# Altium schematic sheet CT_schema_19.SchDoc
size 634 x 434 mm
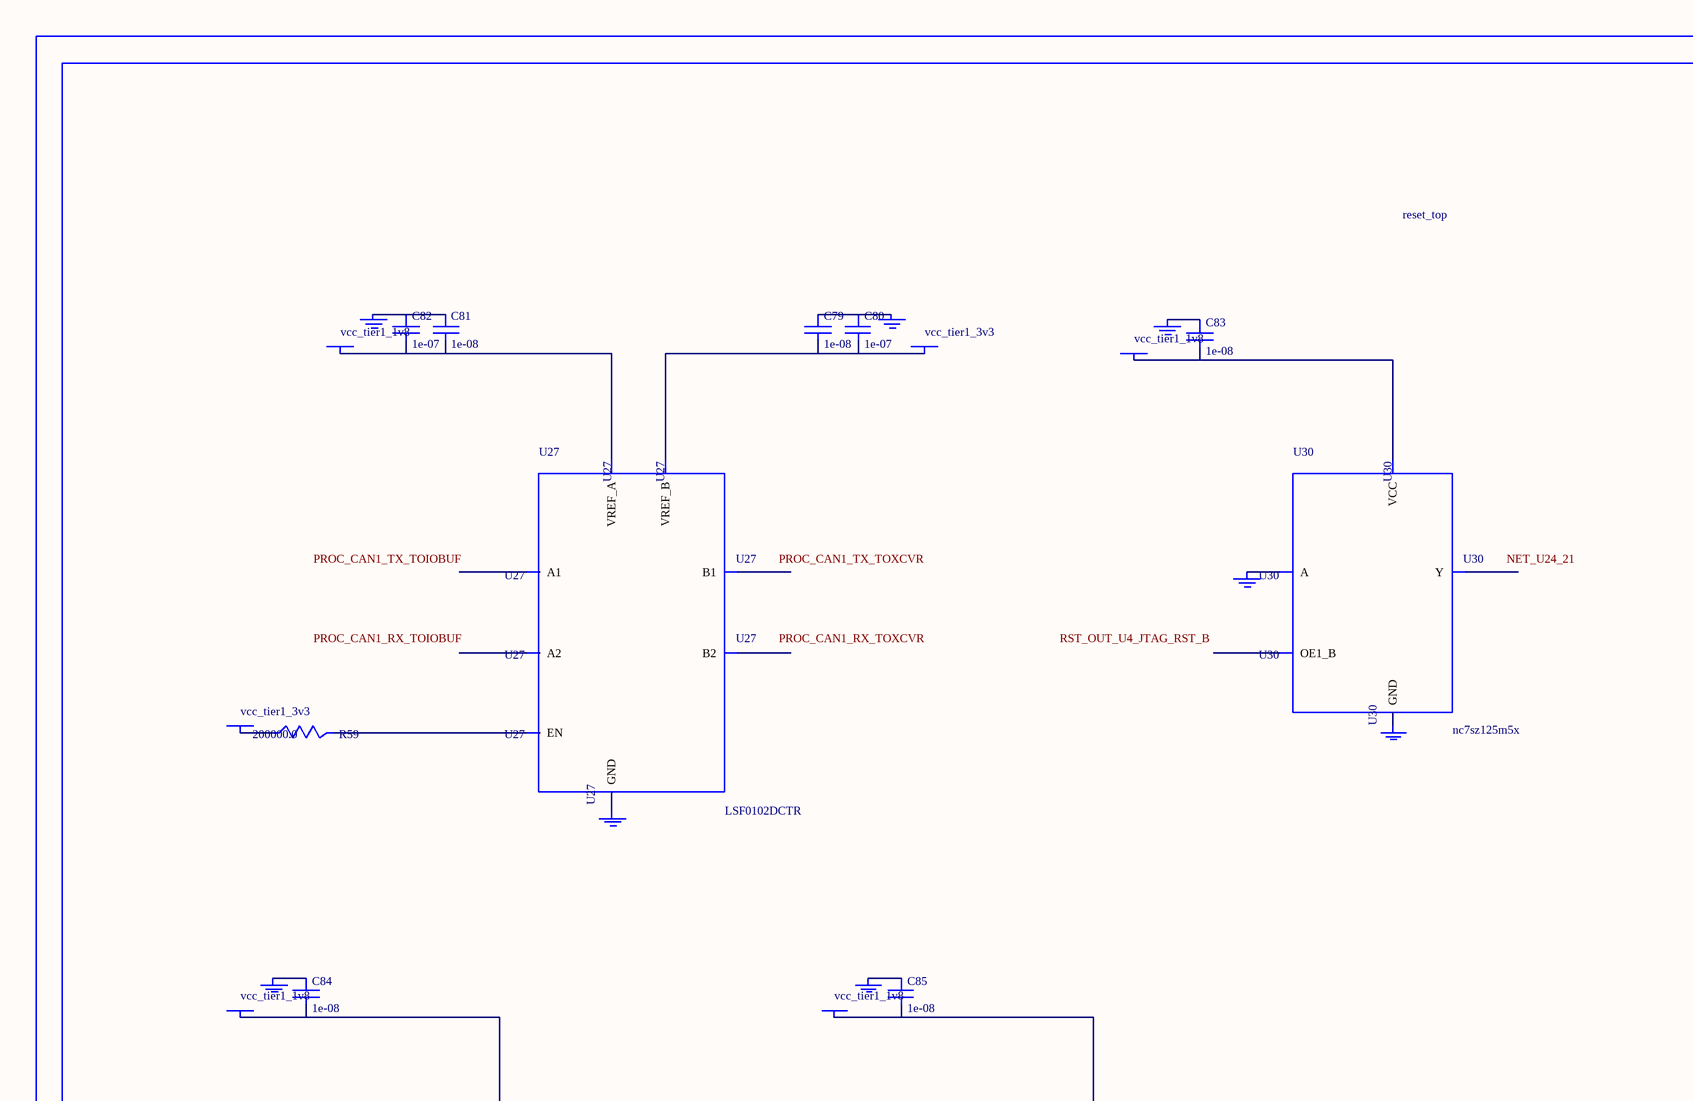
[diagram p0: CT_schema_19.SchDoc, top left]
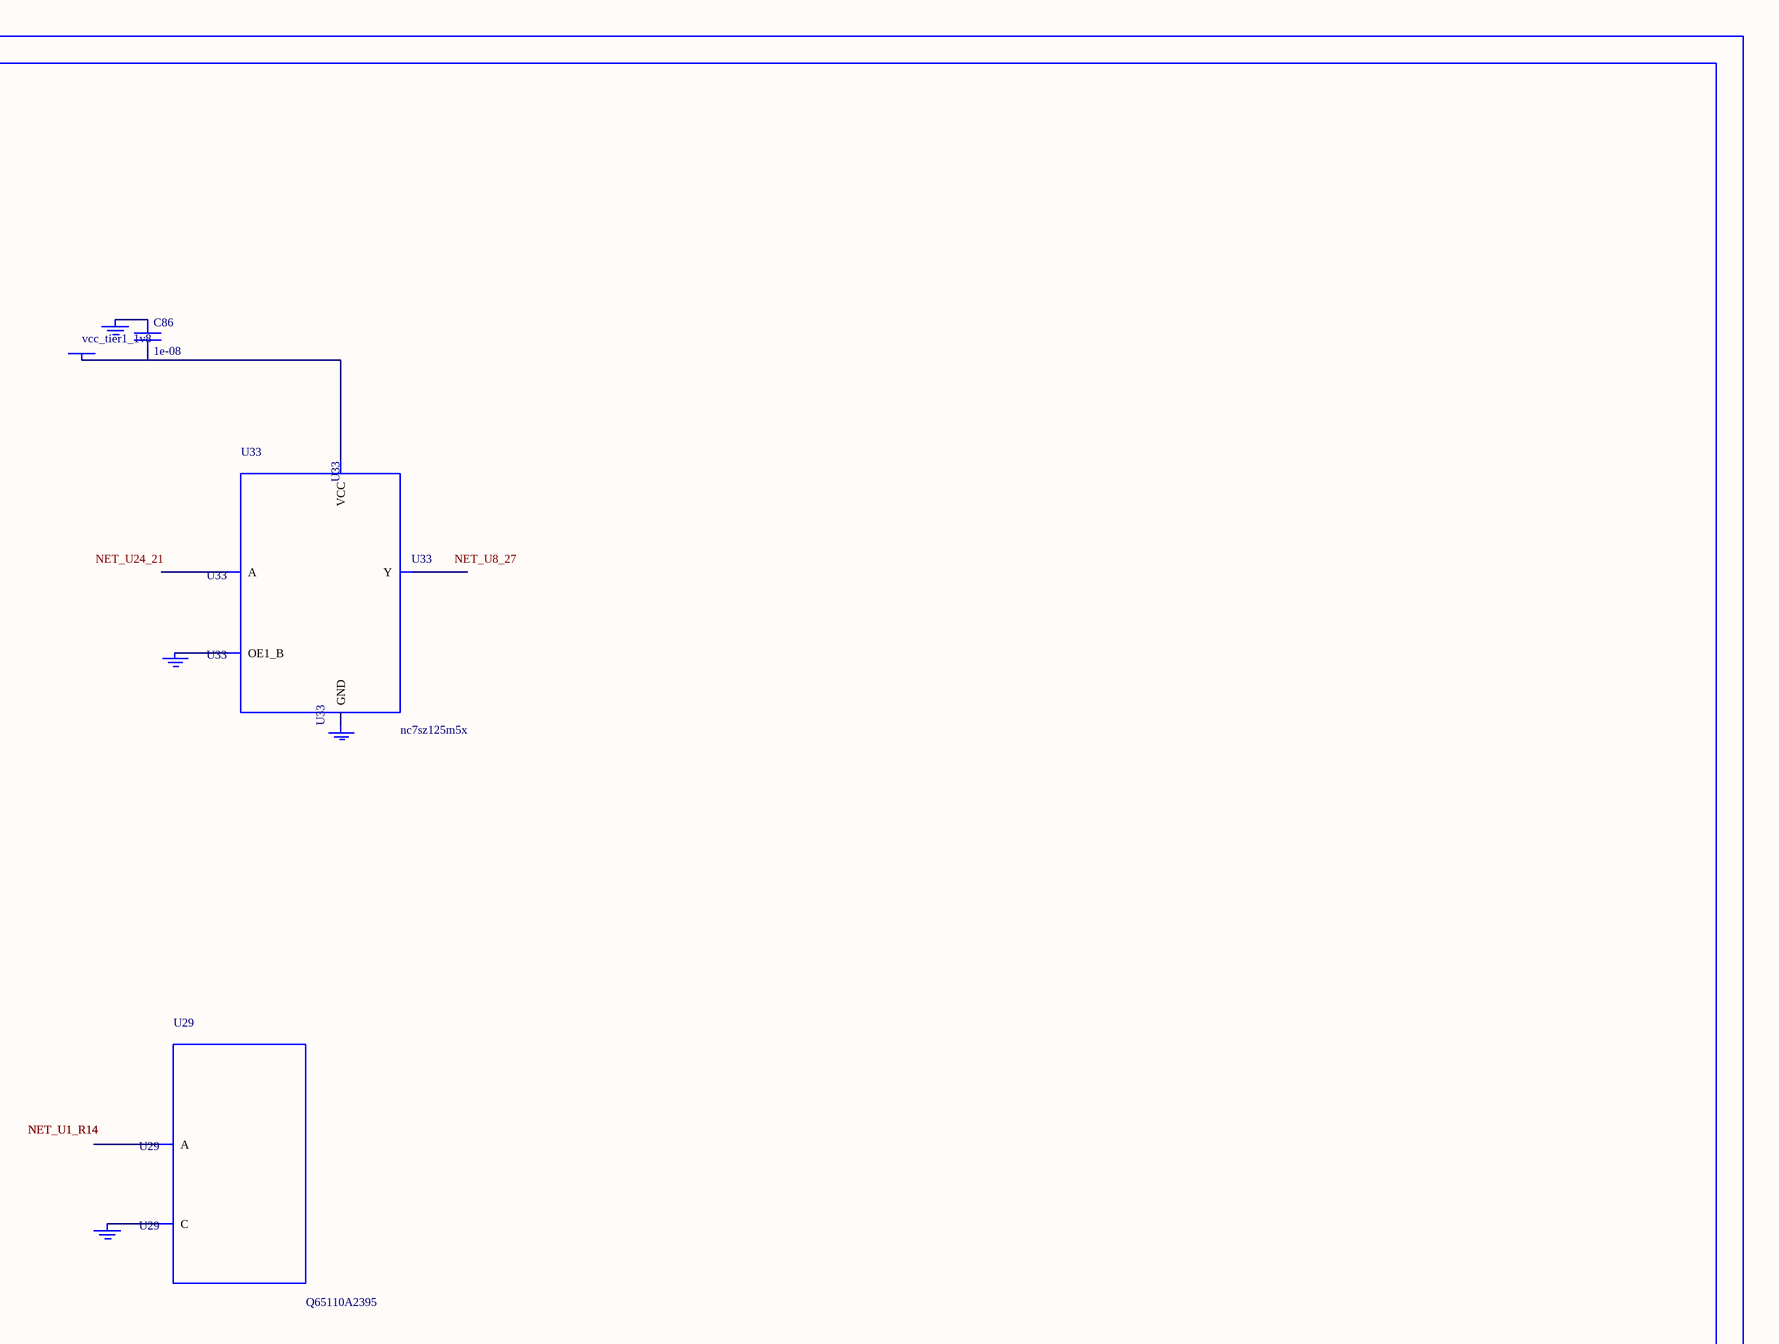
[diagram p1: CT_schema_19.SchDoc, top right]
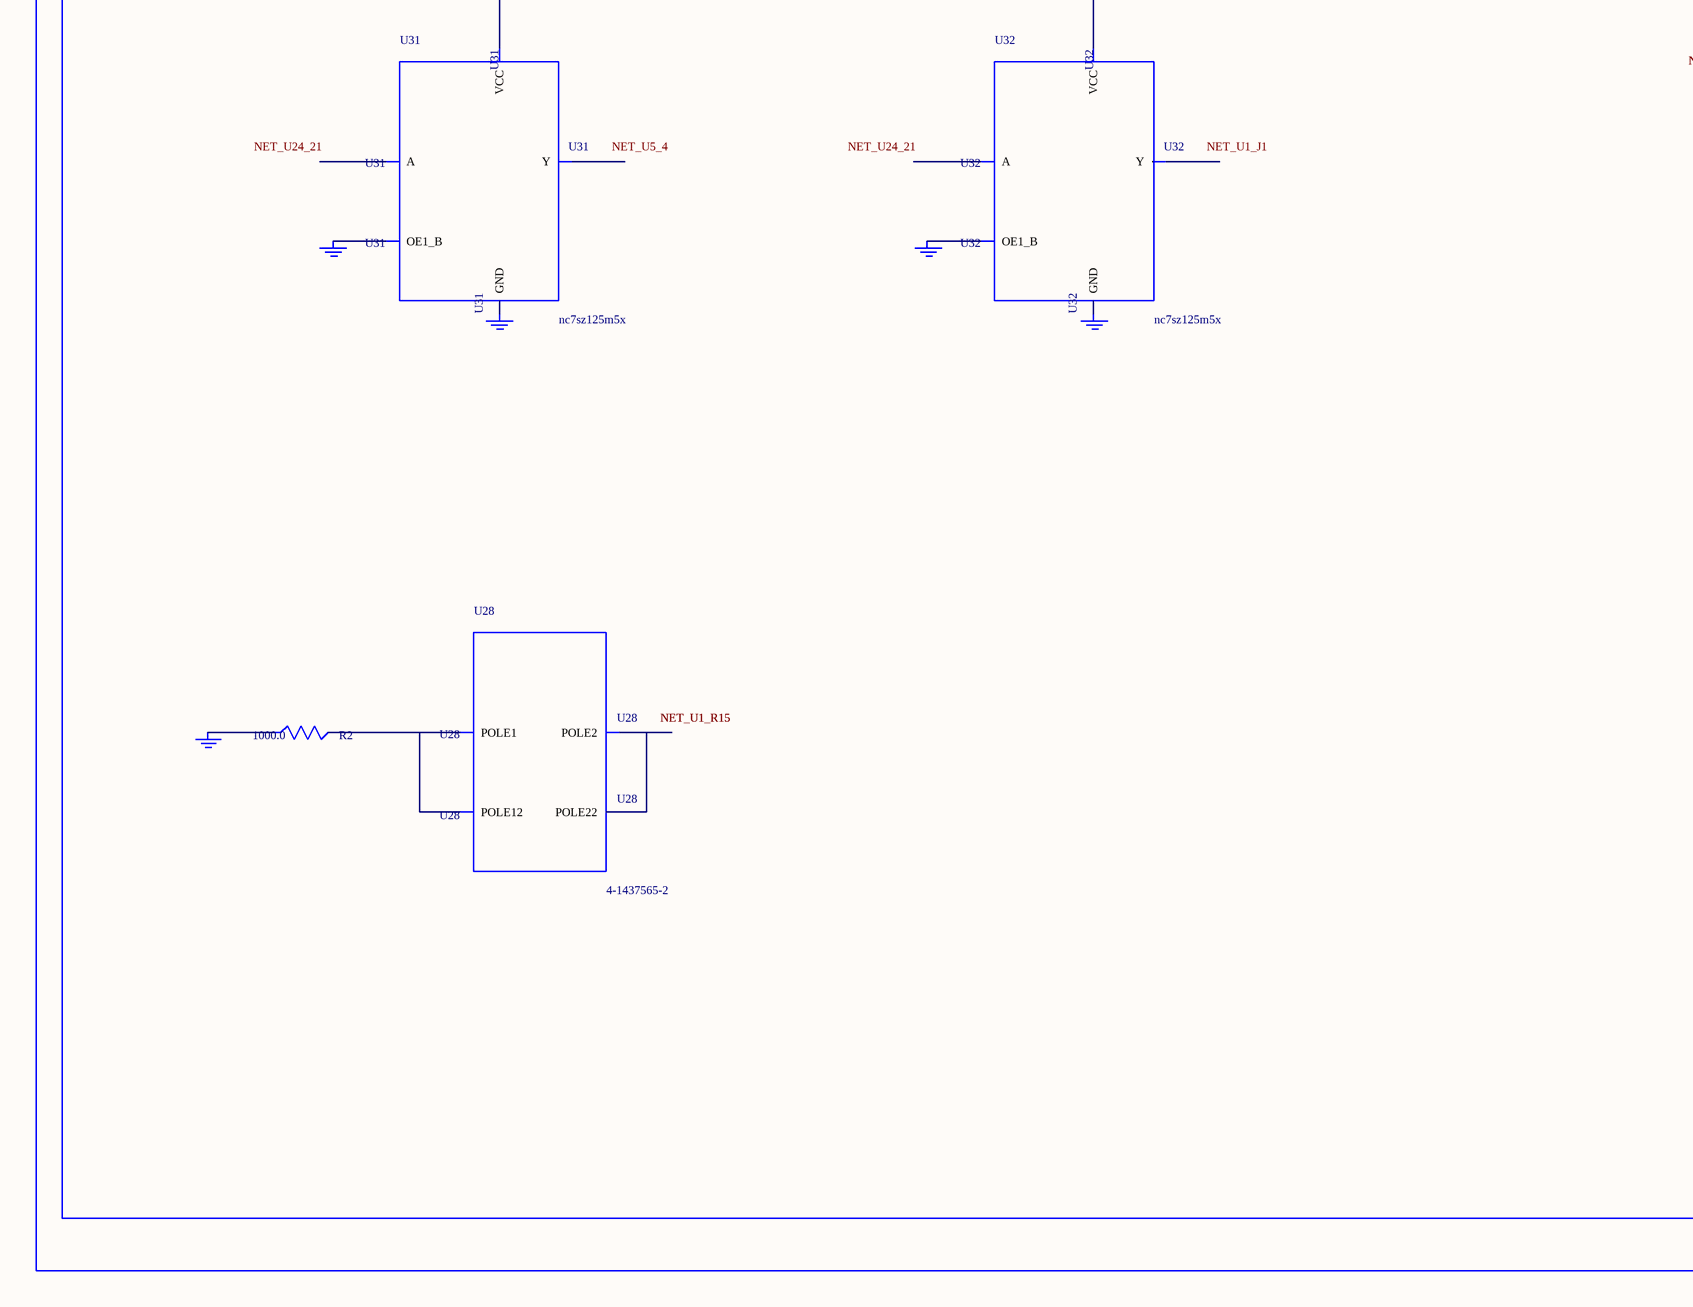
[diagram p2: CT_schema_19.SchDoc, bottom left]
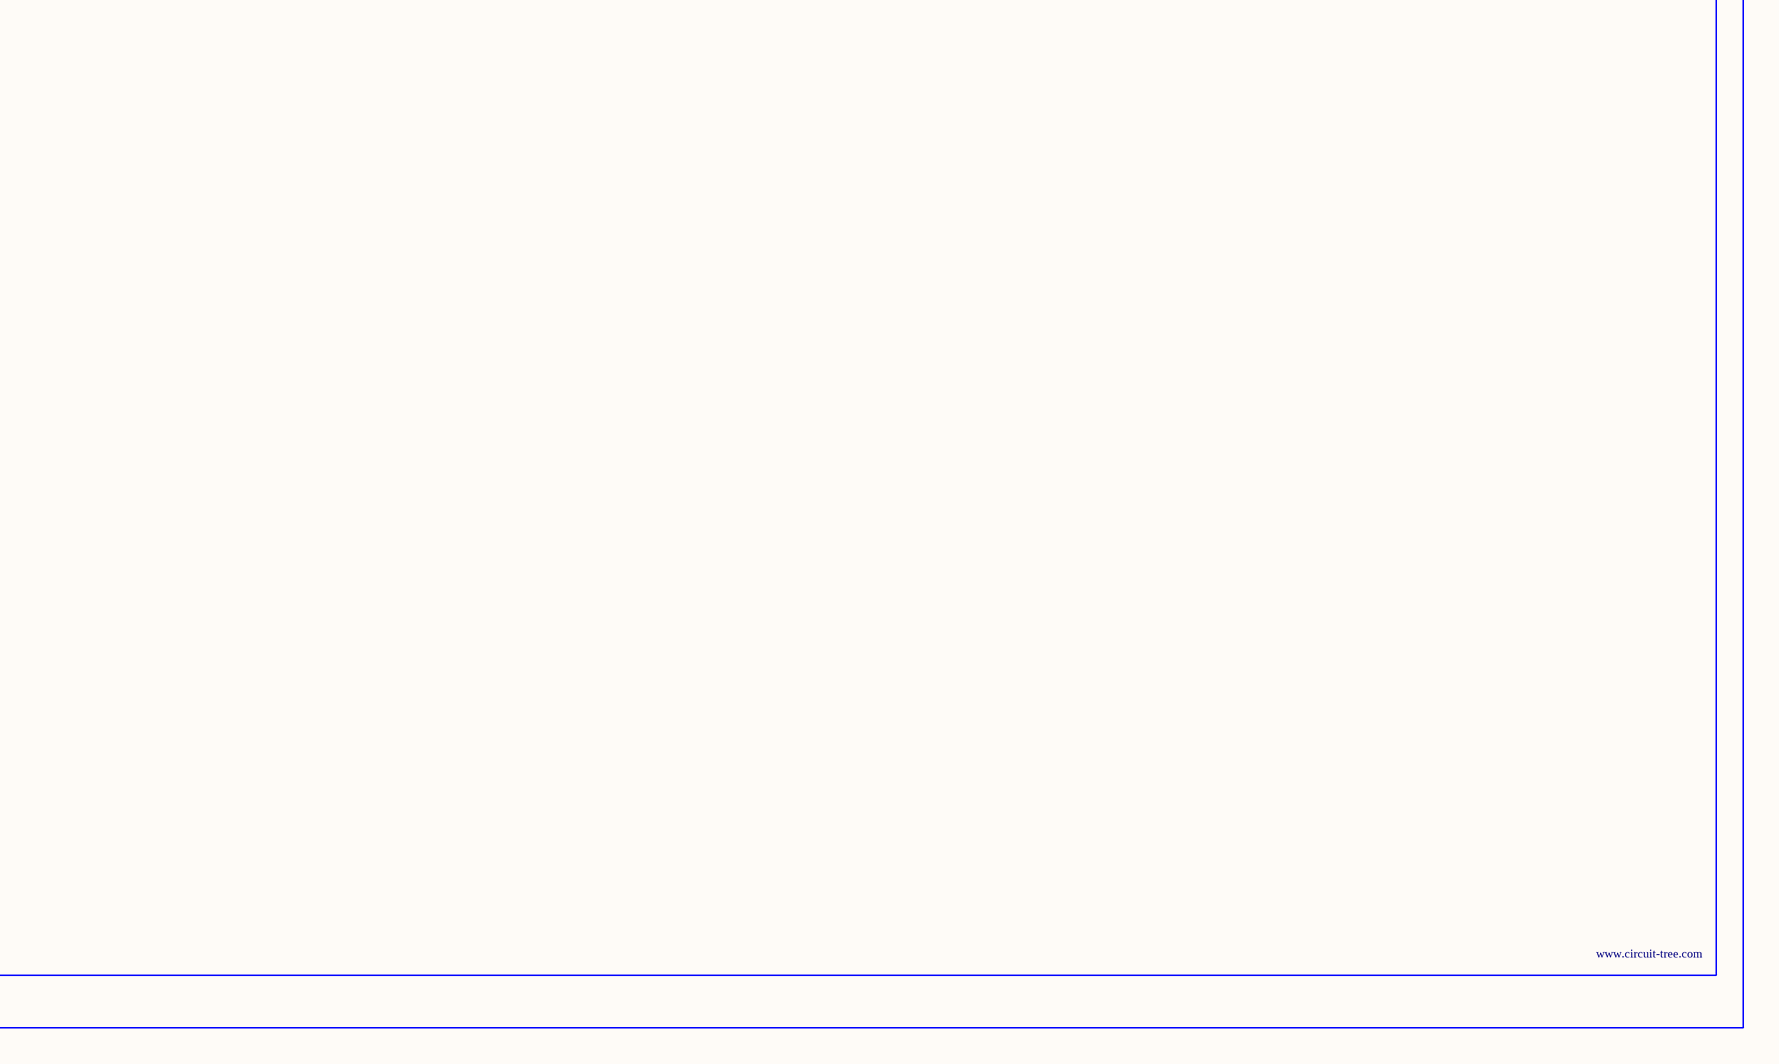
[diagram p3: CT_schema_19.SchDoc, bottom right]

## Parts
BORDER18  (no value)
C79  1e-08  [C0402]
C80  1e-07  [C0402]
C81  1e-08  [C0402]
C82  1e-07  [C0402]
C83  1e-08  [C0402]
C84  1e-08  [C0402]
C85  1e-08  [C0402]
C86  1e-08  [C0402]
GND_INSTANCE_18_0  (no value)
GND_INSTANCE_18_1  (no value)
GND_INSTANCE_18_2  (no value)
GND_INSTANCE_18_3  (no value)
GND_INSTANCE_18_4  (no value)
GND_INSTANCE_18_5  (no value)
GND_INSTANCE_18_6  (no value)
GND_INSTANCE_18_7  (no value)
GND_INSTANCE_18_8  (no value)
GND_INSTANCE_18_9  (no value)
GND_INSTANCE_18_10  (no value)
GND_INSTANCE_18_11  (no value)
GND_INSTANCE_18_12  (no value)
GND_INSTANCE_18_13  (no value)
GND_INSTANCE_18_14  (no value)
GND_INSTANCE_18_15  (no value)
GND_INSTANCE_18_16  (no value)
POWER_INSTANCE_18_0  vcc_tier1_1v8
POWER_INSTANCE_18_1  vcc_tier1_3v3
POWER_INSTANCE_18_2  vcc_tier1_3v3
POWER_INSTANCE_18_3  vcc_tier1_1v8
POWER_INSTANCE_18_4  vcc_tier1_1v8
POWER_INSTANCE_18_5  vcc_tier1_1v8
POWER_INSTANCE_18_6  vcc_tier1_1v8
R2  1000.0  [R0603]
R59  200000.0  [R0603]
U27  LSF0102DCTR  [DCU0008A_N]
U28  4-1437565-2  [SW_4-1437565-2]
U29  Q65110A2395  [LGM67K-G1J2-24-Z]
U30  nc7sz125m5x  [NC7SZ125M5X]
U31  nc7sz125m5x  [NC7SZ125M5X]
U32  nc7sz125m5x  [NC7SZ125M5X]
U33  nc7sz125m5x  [NC7SZ125M5X]

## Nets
NetC79_1: C79.1 C80.1 GND_INSTANCE_18_1.0(GND)
NetC79_2: C79.2 C80.2 POWER_INSTANCE_18_1.0(PWR) U27.7(VREF_B)
NetC81_1: C81.1 C82.1 GND_INSTANCE_18_0.0(GND)
NetC81_2: C81.2 C82.2 POWER_INSTANCE_18_0.0(PWR) U27.2(VREF_A)
NetC83_1: C83.1 GND_INSTANCE_18_5.0(GND)
NetC83_2: C83.2 POWER_INSTANCE_18_3.0(PWR) U30.5(VCC)
NetC84_1: C84.1 GND_INSTANCE_18_8.0(GND)
NetC84_2: C84.2 POWER_INSTANCE_18_4.0(PWR) U31.5(VCC)
NetC85_1: C85.1 GND_INSTANCE_18_11.0(GND)
NetC85_2: C85.2 POWER_INSTANCE_18_5.0(PWR) U32.5(VCC)
NetC86_1: C86.1 GND_INSTANCE_18_14.0(GND)
NetC86_2: C86.2 POWER_INSTANCE_18_6.0(PWR) U33.5(VCC)
NetGND_INSTANCE_18_2_0: GND_INSTANCE_18_2.0(GND) U27.1(GND)
NetGND_INSTANCE_18_3_0: GND_INSTANCE_18_3.0(GND) R2.1
NetGND_INSTANCE_18_4_0: GND_INSTANCE_18_4.0(GND) U29.C
NetGND_INSTANCE_18_6_0: GND_INSTANCE_18_6.0(GND) U30.2(A)
NetGND_INSTANCE_18_7_0: GND_INSTANCE_18_7.0(GND) U30.3(GND)
NetGND_INSTANCE_18_9_0: GND_INSTANCE_18_9.0(GND) U31.1(OE1_B)
NetGND_INSTANCE_18_10_0: GND_INSTANCE_18_10.0(GND) U31.3(GND)
NetGND_INSTANCE_18_12_0: GND_INSTANCE_18_12.0(GND) U32.1(OE1_B)
NetGND_INSTANCE_18_13_0: GND_INSTANCE_18_13.0(GND) U32.3(GND)
NetGND_INSTANCE_18_15_0: GND_INSTANCE_18_15.0(GND) U33.1(OE1_B)
NetGND_INSTANCE_18_16_0: GND_INSTANCE_18_16.0(GND) U33.3(GND)
NetPOWER_INSTANCE_18_2_0: POWER_INSTANCE_18_2.0(PWR) R59.1
NetR2_2: R2.2 U28.1(POLE1) U28.2(POLE12)
NetR59_2: R59.2 U27.8(EN)
NetU28_3: U28.3(POLE2) U28.4(POLE22)

Not connected (* = marked no-connect by the designer): U27 3(A1) 4(A2) 5(B2) 6(B1); U29 A; U30 1(OE1_B) 4(Y); U31 2(A) 4(Y); U32 2(A) 4(Y); U33 2(A) 4(Y)

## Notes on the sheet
- Labels drawn without touching a wire or pin: NET_U1_J1, NET_U5_4, NET_U8_27, NET_U24_21, PROC_CAN1_RX_TOIOBUF, PROC_CAN1_RX_TOXCVR, PROC_CAN1_TX_TOIOBUF, PROC_CAN1_TX_TOXCVR, RST_OUT_U4_JTAG_RST_B

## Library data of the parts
BORDER18 = BORDER_PAGE18
C79 C81 C83-C86 = C0402C103K3RAC
C80 C82 = C0402C104K3RACTU
GND_INSTANCE_18_0-GND_INSTANCE_18_16 = GND
POWER_INSTANCE_18_0-POWER_INSTANCE_18_6 = PWR
R2 = RC0603JR-071KL
R59 = RC0603JR-07200KL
